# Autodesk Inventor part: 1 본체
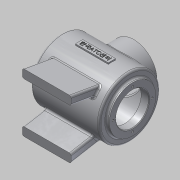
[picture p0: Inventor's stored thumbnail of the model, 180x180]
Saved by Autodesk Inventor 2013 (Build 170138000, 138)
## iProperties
Created: 2015-01
Part Number: 1 본체
Material: 알루미늄 6061
Document SubType Name: Modeling
Designer: Administrator
Density: 2.71 g/cm^3
Mass: 1019.02 g
Surface Area: 1069.83 cm^2
Volume: 376.023 cm^3
Author: Administrator
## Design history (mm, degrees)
sketch "스케치1"
  geometry: C1 r 50 at (0, 0); 1 further point
  constraints: 1 centre point, 1 coincident
  dimensions: "d0" = 100 diameter of C1
extrude "돌출1" new body sketch "스케치1" stored distance "d2" = 112; taper "d3" = 0 deg
sketch "스케치2"
  geometry: C1 r 50 at (0, 0) reference; C2 r 38 at (0, 0)
  constraints: 1 centre point, 1 coincident
  dimensions: "d4" = 76 diameter of C2
extrude "돌출2" join sketch "스케치2" distance "d5" = 5; taper "d6" = 0 deg
sketch "스케치4"
  geometry: L1 (61, 38)-(61, -38) reference; L2 (-61, 38)-(-61, -38) reference; L3 (49, -45)-(49, 0); L4 (-48, -45)-(-48, 0); L5 (61, 0)-(61, -27); L6 (61, -27)-(49, -27); L7 (-61, 0)-(-61, -27); L8 (-61, -27)-(-48, -27); L9 (-56, 50)-(-56, -50) reference; L10 (56, -50)-(56, 50) reference; L11 (49, -45)-(-48, -45) reference; 3 further points
  constraints: 14 end point, 4 point on line, 3 perpendicular, 2 midpoint, 2 vertical, 1 horizontal, 1 vertical alignment, 6 other
  dimensions: "d11" = 54 dimension on L8; "d12" = 54 dimension on L6; "d59" = 7 distance between parallel lines of L10 L3; "d60" = 8 distance between parallel lines of L9 L4; "d61" = 97 distance of L3.start L4.start (derived); "d62" = 90 dimension on L11 (derived)
revolve "회전1" sketch "스케치4" stored, may be unused: angle "d14" = 90 deg
node "작업 평면1"
sketch "스케치5"
  geometry: L1 (-27, -6)-(27, -6); L2 (27, -6)-(27, 6); L3 (27, 6)-(-27, 6); L4 (-27, 6)-(-27, -6); L5 (-27, -6)-(27, 6); L6 (27, -6)-(-27, 6); 1 further point
  constraints: 12 end point, 2 midpoint, 2 parallel, 1 horizontal, 1 perpendicular
  dimensions: "d15" = 54 distance of L2.end L3.end; "d17" = 12 distance of L1.end L2.end
extrude "돌출3" join sketch "스케치5" distance "d18" = 2; taper "d20" = 0 deg; dims "d19" = 3, "d21" = 0
sketch "스케치6"
  geometry: L1 (-24.887, 3.602)-(24.887, 3.602); L2 (24.887, 3.602)-(24.887, -3.602); L3 (24.887, -3.602)-(-24.887, -3.602); L4 (-24.887, -3.602)-(-24.887, 3.602); L5 (-24.887, 3.602)-(24.887, -3.602); L6 (-24.887, -3.602)-(24.887, 3.602); 2 further points
  constraints: 4 end point, 1 coincident, 1 midpoint, 2 other
feature "엠보싱1" sketch "스케치6" dims "d11" = 54, "d12" = 54, "d22" = 0.5, "d23" = 0, "d59" = 7, "d60" = 8, "d61" = 97 (derived), "d62" = 90 (derived)
sketch "스케치7"
  geometry: L1 (0, 0)-(-80, 0); L2 (-80, 48)-(-80, -48); L3 (-80, -48)-(-30.865, -39.336); L4 (-80, -34)-(-41.901, -27.282); L5 (-80, 48)-(-30.865, 39.336); L6 (-80, 34)-(-41.901, 27.282); A1 r 50 centre (0, 0) between (-30.865, -39.336) and (-41.901, -27.282) reference
  constraints: 12 end point, 4 point on circle, 2 parallel, 2 point on line, 1 horizontal, 1 midpoint, 1 perpendicular
  dimensions: "d25" = 80 distance of L1.end L1.start; "d26" = 96 distance of L2.start L2.end; "d27" = 100 deg angle of L3 L2; "d28" = 14 distance of L2.end L4.start; "d29" = 80 deg angle of L2 L4 (derived); "d30" = 14 distance of L6.start L2.start; "d31" = 100 deg angle of L2 L5; "d32" = 80 deg angle of L2 L6 (derived)
extrude "돌출4" join sketch "스케치7" stored distance "d33" = 80; taper "d34" = 0 deg
node "작업 평면3"
node "작업 평면4"
sketch "스케치11"
  geometry: L1 (61, 38)-(61, -38) reference; L2 (-61, 38)-(-61, -38) reference; C1 r 38 at (-1, 0); 1 further point
  constraints: 1 centre point, 1 horizontal alignment
  dimensions: "d101" = 60 distance from line of L2 C1.centre; "d102" = 62 distance from line of C1.centre L1 (derived); "d103" = 76 diameter of C1
extrude "돌출8" join sketch "스케치11" stored distance "d67" = 80; taper "d68" = 0 deg
sketch "스케치14" dims "d84" = 64
  geometry: C1 r 27 at (0, 0) reference; C2 r 38 at (0, 0) reference; 5 further points
  constraints: 2 vertical alignment, 1 coincident, 7 other
  dimensions: "d87" = 360 deg dimension on point (0, 0) point (0, 32) (derived)
hole "구멍3" sketch "스케치14" at (0, 32), (-32, 0), (0, -32), (32, 0) diameter "d89" = 3.242; stored, may be unused: countersink angle "d93" = 90 deg, drill point angle "d95" = 118 deg; dims "d90" = 8, "d91" = 4, "d92" = 2, "d94" = 10
chamfer "모따기1" distance "d96" = 1; stored, may be unused: second distance "d97" = 2, angle "d98" = 45 deg
fillet "모깎기1" dims "d99" = 3
sketch "스케치15"
  geometry: C1 r 38 at (0, 0) reference; C2 r 27 at (0, 0); 1 further point
  constraints: 1 centre point, 1 coincident
  dimensions: "d104" = 54 diameter of C2
extrude "돌출10" cut sketch "스케치15" stored distance "d105" = 80; taper "d106" = 0 deg
sketch "스케치16" dims "d108" = 64
  geometry: C1 r 27 at (0, 0) reference; C2 r 38 at (0, 0) reference; 6 further points
  constraints: 2 vertical alignment, 1 coincident, 7 other
  dimensions: "d111" = 360 deg dimension on point (0, 0) point (0, 32) (derived)
hole "구멍4" sketch "스케치16" at (0, 32), (-32, 0), (0, -32), (32, 0) diameter "d113" = 3.242; stored, may be unused: countersink angle "d117" = 90 deg, drill point angle "d119" = 118 deg; dims "d114" = 8, "d115" = 4, "d116" = 2, "d118" = 10
fillet "모깎기2" dims "d120" = 3
chamfer "모따기2" distance "d121" = 1; stored, may be unused: second distance "d122" = 2, angle "d123" = 45 deg
node "솔리드1"
mirror "대칭2"
mirror "대칭3"
other parameters: "d35" = 62, "d65" = 62
